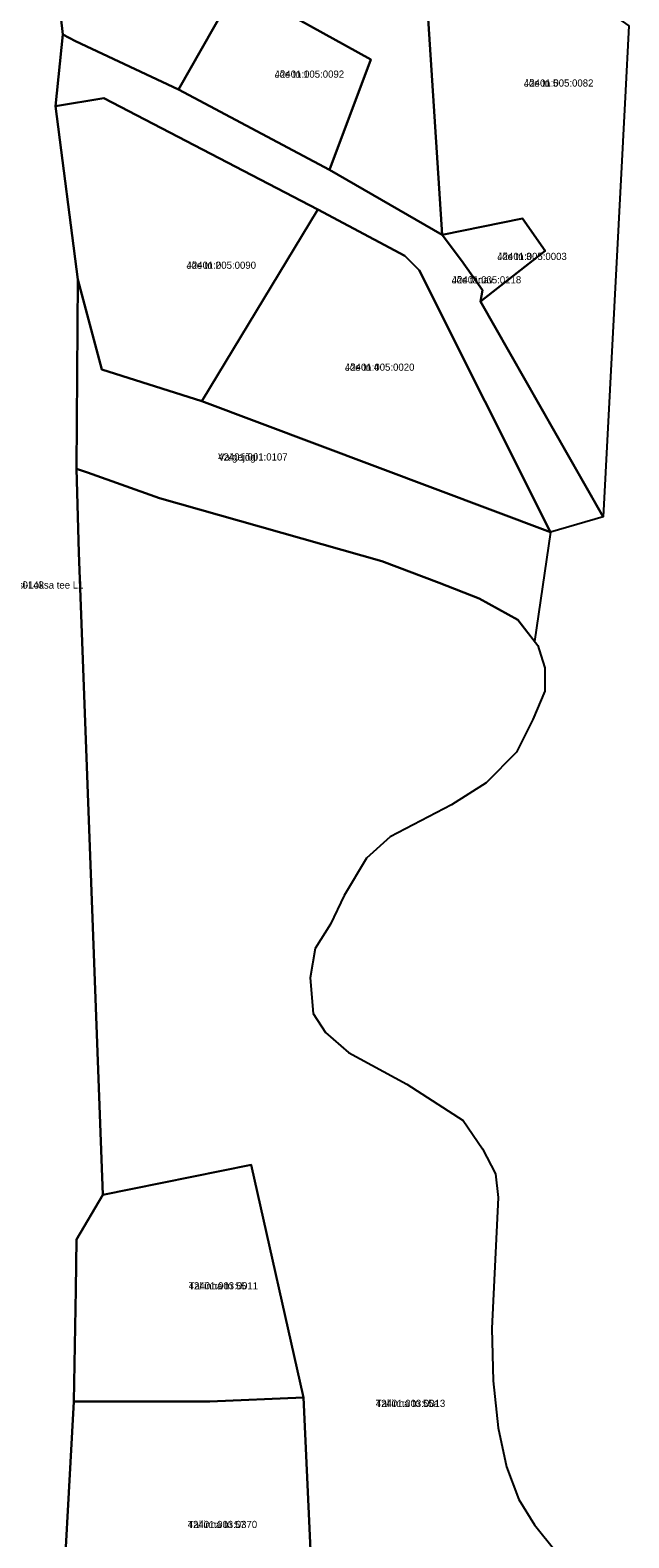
# Model space of a CAD drawing. Extents: x 595979 to 597983, y 6604231 to 6607350.
# Drawn here: x 597489.5 to 597614.5, y 6605469.2 to 6605784.1 of the extents above; entities that cross this region are included whole.
import ezdxf

# ---------------------------------------------------------------- set-up
doc = ezdxf.new("R2010")
doc.units = 0
for name, color, linetype in [('L_AADRESS', 7, 'Continuous'), ('PIIR', 7, 'Continuous'), ('TUNNUS', 7, 'Continuous')]:
    doc.layers.add(name, color=color, linetype=linetype)

msp = doc.modelspace()

# ---------------------------------------------------------------- linework, layer by layer
at = {"layer": 'PIIR'}
for points in [[(597483.61, 6605418.8), (597487.25, 6605511.01), (597485.88, 6605529.34), (597483.58, 6605588.75), (597477.72, 6605704.26), (597472.63, 6605758.73), (597472.15, 6605763.69), (597470.46, 6605791.65), (597465.11, 6605849.2), (597488.98, 6605855.16), (597490.09, 6605844.44), (597491.22, 6605839.74), (597491.66, 6605823.87), (597496.25, 6605783.15), (597494.72, 6605768.17), (597499.41, 6605731.99), (597499.16, 6605692.44), (597499.62, 6605675), (597504.66, 6605540.85), (597499.14, 6605531.46), (597498.96, 6605521.02), (597498.55, 6605497.68), (597495.69, 6605445.75)], [(597549.02, 6605443.81), (597546.56, 6605498.49), (597535.64, 6605547.09), (597504.66, 6605540.85), (597499.62, 6605675), (597499.16, 6605692.44), (597501.44, 6605691.7), (597516.45, 6605686.36), (597562.87, 6605673.17), (597574.84, 6605668.68), (597583.23, 6605665.38), (597591.27, 6605660.92), (597595.49, 6605655.53), (597596.12, 6605653.51), (597596.93, 6605650.89), (597596.91, 6605646.05), (597594.45, 6605640.07), (597591.05, 6605633.25), (597584.7, 6605626.87), (597577.42, 6605622.28), (597564.66, 6605615.62), (597559.69, 6605611.13), (597555.02, 6605603.37), (597552.15, 6605597.39), (597548.96, 6605592.25), (597547.93, 6605586.18), (597548.54, 6605578.69), (597551.14, 6605574.76), (597555.96, 6605570.53), (597568.12, 6605563.94), (597579.85, 6605556.34), (597583.89, 6605550.41), (597586.64, 6605545.22), (597587.17, 6605540.25), (597585.87, 6605512.93), (597586.13, 6605501.99), (597587.16, 6605492.15), (597588.92, 6605483.99), (597591.53, 6605477.2), (597594.79, 6605471.88), (597612.87, 6605449.35)]]:
    msp.add_lwpolyline(points, dxfattribs=at)
for points in [[(597491.66, 6605823.87), (597494.65, 6605823.92), (597508.61, 6605824.37), (597514.82, 6605842.05), (597532.07, 6605833.45), (597550.76, 6605824.49), (597570.69, 6605815.52), (597575.47, 6605741.32), (597551.99, 6605754.92), (597560.61, 6605777.97), (597532.74, 6605793.38), (597520.45, 6605771.68), (597498.93, 6605781.76), (597496.25, 6605783.15)], [(597609.15, 6605682.42), (597583.48, 6605727.39), (597596.98, 6605737.97), (597592.27, 6605744.76), (597575.47, 6605741.32), (597570.69, 6605815.52), (597614.48, 6605785.01), (597613.71, 6605770.11)], [(597520.45, 6605771.68), (597532.74, 6605793.38), (597560.61, 6605777.97), (597551.99, 6605754.92)], [(597496.25, 6605783.15), (597498.93, 6605781.76), (597520.45, 6605771.68), (597551.99, 6605754.92), (597575.47, 6605741.32), (597579.55, 6605735.98), (597583.89, 6605729.74), (597583.48, 6605727.39), (597604.61, 6605690.38), (597609.15, 6605682.42), (597598.09, 6605679.24), (597570.72, 6605733.98), (597567.72, 6605736.91), (597549.52, 6605746.65), (597504.87, 6605769.88), (597494.72, 6605768.17)], [(597549.52, 6605746.65), (597525.31, 6605706.57), (597504.43, 6605713.17), (597499.41, 6605731.99), (597494.72, 6605768.17), (597504.87, 6605769.88)], [(597567.72, 6605736.91), (597570.72, 6605733.98), (597598.09, 6605679.24), (597525.31, 6605706.57), (597549.52, 6605746.65)], [(597583.89, 6605729.74), (597579.55, 6605735.98), (597575.47, 6605741.32), (597592.27, 6605744.76), (597596.98, 6605737.97), (597583.48, 6605727.39)], [(597598.09, 6605679.24), (597594.81, 6605656.39), (597591.27, 6605660.92), (597583.23, 6605665.38), (597574.84, 6605668.68), (597562.87, 6605673.17), (597516.45, 6605686.36), (597501.44, 6605691.7), (597499.16, 6605692.44), (597499.41, 6605731.99), (597504.43, 6605713.17), (597525.31, 6605706.57)], [(597498.96, 6605521.02), (597499.14, 6605531.46), (597504.66, 6605540.85), (597535.64, 6605547.09), (597546.56, 6605498.49), (597526.95, 6605497.69), (597498.55, 6605497.68)], [(597498.55, 6605497.68), (597526.95, 6605497.69), (597546.56, 6605498.49), (597549.02, 6605443.81), (597495.69, 6605445.75)]]:
    msp.add_lwpolyline(points, close=True, dxfattribs=at)

# ---------------------------------------------------------------- texts
at = {"layer": 'L_AADRESS'}
for s, p in [('Jõe tn 1', (597540.52, 6605774.15)), ('Jõe tn 5', (597592.58, 6605772.29)), ('Jõe tn 2', (597522.12, 6605734.24)), ('Jõe tn 3', (597587.02, 6605736.08)), ('Jõe tänav', (597577.5, 6605731.19)), ('Jõe tn 4', (597555.2, 6605712.94)), ('Valgejõgi', (597528.72, 6605694.19)), ('85 Liiapeksi-Loksa tee L1', (597477.83, 6605667.44)), ('Tallinna tn 55', (597522.55, 6605521.07)), ('Tallinna tn 55a', (597561.64, 6605496.52)), ('Tallinna tn 57', (597522.36, 6605471.23))]:
    msp.add_text(s, height=1.5, dxfattribs=at).set_placement(p)
at = {"layer": 'TUNNUS'}
for s, p in [('42401:005:0092', (597540.52, 6605774.15)), ('42401:005:0082', (597592.58, 6605772.29)), ('42401:005:0090', (597522.12, 6605734.24)), ('42401:005:0003', (597587.02, 6605736.08)), ('42401:005:0118', (597577.5, 6605731.19)), ('42401:005:0020', (597555.2, 6605712.94)), ('42401:001:0107', (597528.72, 6605694.19)), ('42401:001:0143', (597477.83, 6605667.44)), ('42401:003:0011', (597522.55, 6605521.07)), ('42401:003:0013', (597561.64, 6605496.52)), ('42401:003:0370', (597522.36, 6605471.23))]:
    msp.add_text(s, height=1.5, dxfattribs=at).set_placement(p)

doc.saveas('drawing.dxf')
